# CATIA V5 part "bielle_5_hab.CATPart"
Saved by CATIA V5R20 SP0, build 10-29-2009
Part number: bielle_5_hab
Bounding box of the stored display mesh (mm): x 0.1 to 0.15, y 1.42 to 2.18, z 1.07 to 1.5
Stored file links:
  D:\Dropbox\IAO_2012\IAO_2012_718_ccascaro\ccascaro\bielle_5_hab.CATPart
  C:\Users\Cédric\Documents\IFMA-2A\IAO\Projet IAO\Projet IAO catia\ass_bielles_skl.CATProduct
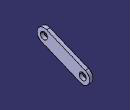
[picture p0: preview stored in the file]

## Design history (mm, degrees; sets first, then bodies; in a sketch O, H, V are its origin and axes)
Set1
  Point1 "point G": linked copy from another document
  Point2 "point F": linked copy from another document
Body1 (main body)
  Sketch1 on yz-plane, origin (0, 0, 0), H (0, 1, 0), V (0, 0, 1)
    construction line L1 (1.52, 1.4) -> (2.08, 1.17)
    point P1 (1.52, 1.4)
    point P2 (2.08, 1.17)
    line L2 (1.558, 1.4925) -> (2.118, 1.2625)
    line L3 (2.042, 1.0775) -> (1.482, 1.3075)
    arc A1 centre (2.08, 1.17) radius 0.1 from (2.118, 1.2625) to (2.042, 1.0775) cw
    arc A2 centre (1.52, 1.4) radius 0.1 from (1.482, 1.3075) to (1.558, 1.4925) cw
    reference projected point E1 (2.08, 1.17) from Point1
    reference projected point E2 (1.52, 1.4) from Point2
    circle A3 centre (2.08, 1.17) radius 0.05
    circle A4 centre (1.52, 1.4) radius 0.05
    distance L1 L2 = 0.1
    distance P2 E1 = 0
    distance E2 P1 = 0
    tangency: A1 L2, A2 L2, A1 L3, A2 L3
  Pad1: profile Sketch1, direction (1, 0, 0), length 0.1, opposite side length -0.15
